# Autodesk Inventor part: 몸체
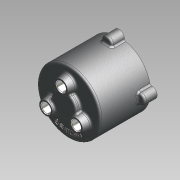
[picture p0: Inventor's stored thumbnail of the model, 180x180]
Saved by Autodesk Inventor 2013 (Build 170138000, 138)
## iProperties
Company: 한국ATC센터
Created: 2014-07
Part Number: 몸체
Document SubType Name: 모델링
Designer: KYOUNG IL JANG
Material: 알루미늄 6061
Mass: 475.555 g
Surface Area: 687.659 cm^2
Volume: 175.481 cm^3
Density: 2.71 g/cm^3
변환 표준: STEP AP214IS
파일 이름: C:\Users\SeoGD\Desktop\?쒗뿕\紐몄껜.stp
전처리기: Build: 253, Release: 2010 SP1 - Date: Wed 07/29/2009
전송 단위: 밀리미터
불확실성: 0.01
Author: KYOUNG IL JANG
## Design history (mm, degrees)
sketch "스케치2"
  geometry: C1 r 50 at (0, 0); 1 further point
  constraints: 1 centre point, 1 coincident
  dimensions: "d9" = 100 diameter of C1
extrude "돌출2" new body sketch "스케치2" distance "d10" = 80; taper "d11" = 0 deg
feature "쉘1" dims "d12" = 5
sketch "스케치3" dims "d13" = 55
  geometry: C1 r 7.5 at (0, 27.5); C2 r 12.5 at (0, 27.5); 2 further points
  constraints: 2 centre point, 2 coincident, 2 vertical alignment, 2 other
  dimensions: "d14" = 15 diameter of C1; "d15" = 25 diameter of C2
extrude "돌출3" join sketch "스케치3" distance "d16" = 12; taper "d17" = -10 deg
hole "구멍2" diameter "d20" = 15; stored, may be unused: countersink angle "d24" = 90 deg, drill point angle "d26" = 118 deg; dims "d18" = 10, "d19" = 10, "d21" = 6, "d22" = 4, "d23" = 2, "d25" = 15
chamfer "모따기1" distance "d27" = 1; stored, may be unused: second distance "d28" = 2, angle "d29" = 45 deg
sketch "스케치4"
  geometry: L1 (0, 0)-(0, 88); L2 (0, 70)-(13.16, 70); L3 (-45, 75)-(45, 75) reference; L4 (-50, 80)-(50, 80) reference; L5 (13.16, 70)-(14.5, 75); L6 (20, 80)-(20, 88); L7 (20, 88)-(0, 88); L8 (20, 80)-(14.5, 75)
  constraints: 12 end point, 3 point on line, 2 perpendicular, 1 vertical
  dimensions: "d34" = 40 diameter of L6 L1; "d35" = 105 deg angle of L5 L3; "d36" = 5 distance between parallel lines of L2 L3; "d37" = 8 distance between parallel lines of L7 L4; "d51" = 29 diameter of L5.end L1
revolve "회전1" sketch "스케치4" stored, may be unused: angle "d38" = 90 deg
hole "구멍3" diameter "d41" = 15; stored, may be unused: countersink angle "d45" = 90 deg, drill point angle "d47" = 0 deg; dims "d39" = 10, "d40" = 10, "d42" = 6, "d43" = 22, "d44" = 13, "d46" = 15
chamfer "모따기2" distance "d48" = 1; stored, may be unused: second distance "d49" = 2, angle "d50" = 45 deg
fillet "모깎기1" dims "d52" = 3
fillet "모깎기2" dims "d53" = 3, "d72" = 0.2
sketch "스케치5"
  geometry: A1 r 50 centre (0, 0) between (50, 0) and (-8.074, 49.344) reference; A2 r 8.5 centre (0, 52) between (8.074, 49.344) and (-8.074, 49.344); 1 further point
  constraints: 5 point on circle, 1 centre point, 1 horizontal alignment
  dimensions: "d54" = 90 deg dimension on point (0, 0) A2.centre A1.start; "d55" = 52 distance of A2.centre point (0, 0); "d56" = 17 diameter of A2
extrude "돌출4" join sketch "스케치5" distance "d57" = 20; taper "d58" = 0 deg
fillet "모깎기3" dims "d59" = 3
hole "구멍4" diameter "d62" = 4.134; stored, may be unused: countersink angle "d66" = 90 deg, drill point angle "d68" = 118 deg; dims "d60" = 10, "d61" = 10, "d63" = 12, "d64" = 22, "d65" = 13, "d67" = 15
sketch "스케치6"
  geometry: C1 r 47 at (0, 0) reference; C2 r 42.5 at (0, 0); 1 further point
  constraints: 1 centre point, 1 coincident, 1 other
  dimensions: "d73" = 85 diameter of C2
feature "엠보싱1" sketch "스케치6" dims "d74" = 1, "d75" = 0
node "솔리드1"
node "솔리드 본체"
node "곡면 본체"
pattern_circular "원형 패턴1" dims "d31" = 360 deg
pattern_circular "원형 패턴2" dims "d70" = 360 deg
node "솔리드2"
